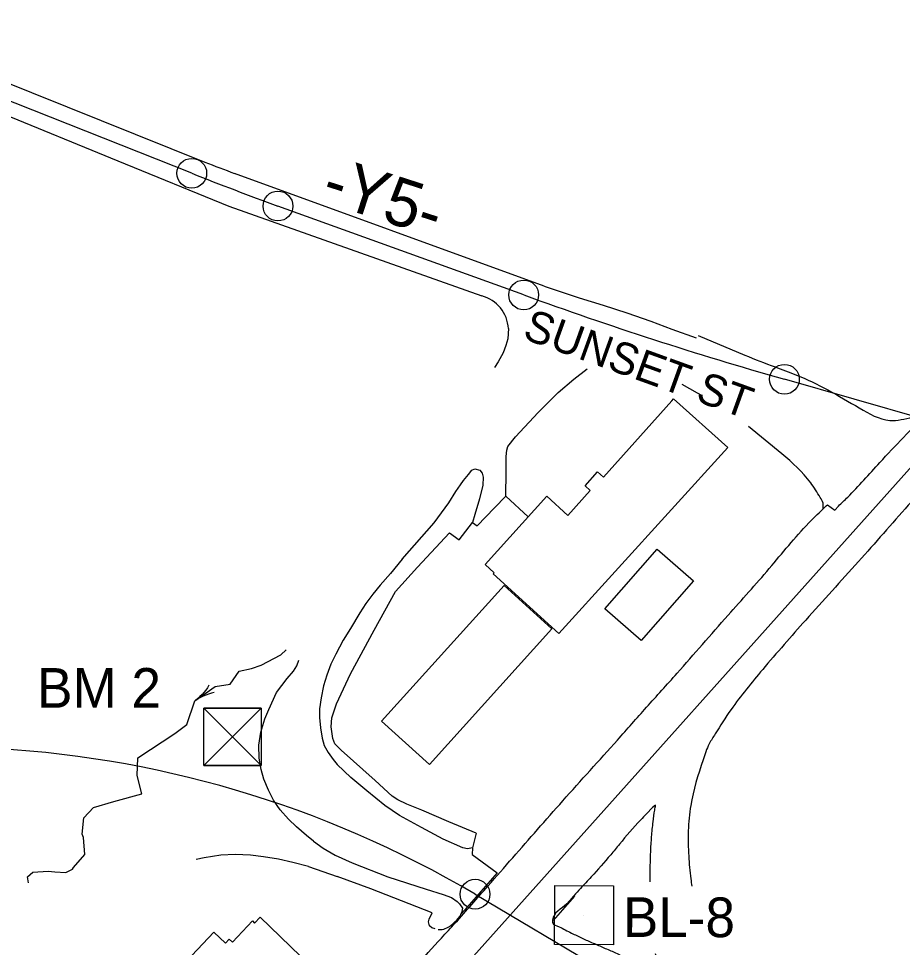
# Model space of a CAD drawing. Extents: x 2088830 to 2093930, y 861854 to 865154.
# Drawn here: x 2091668.1 to 2092113.5, y 863895.4 to 864363.2 of the extents above; entities that cross this region are included whole.
import ezdxf

# ---------------------------------------------------------------- set-up
doc = ezdxf.new("R2010")
doc.units = 0
for name, color, linetype in [('Default', 7, 'Continuous'), ('Exist Building', 7, 'Continuous'), ('Exist Building Metal Canopy', 7, 'Continuous'), ('Exist Horizontal Alignment', 7, 'Continuous'), ('Exist Horizontal Alignment Station Label', 7, 'Continuous'), ('Exist Hydro Stream Flow Arrow CELL', 7, 'Continuous'), ('Exist Hydro Stream or Body of Water', 7, 'Continuous'), ('Exist Roads Curbs', 7, 'Continuous'), ('Exist Roads EOP', 7, 'Continuous'), ('Exist Roads EOP Other', 7, 'Continuous'), ('Exist Roads Soil', 7, 'Continuous'), ('Exist Roads Soil Text', 7, 'Continuous')]:
    doc.layers.add(name, color=color, linetype=linetype)

msp = doc.modelspace()

# ---------------------------------------------------------------- linework, layer by layer
at = {"layer": 'Default'}
for p, q in [((2091668.57, 863635.39), (2092319.98, 864363.19)), ((2091755.37, 864285.26), (2091585.51, 864352.73)), ((2091922.65, 864223.98), (2091798.81, 864268.79)), ((2092136.35, 864158.02), (2092054.04, 864181.52)), ((2091775.92, 864001.45), (2091775.92, 864001.45)), ((2091898.12, 863922.18), (2091993.02, 863866.1)), ((2091952.99, 863911.67), (2091952.99, 863911.67))]:
    msp.add_line(p, q, dxfattribs=at)
for points in [[(2091761.52, 864015.8), (2091790.27, 864015.8), (2091790.27, 863987.05), (2091761.52, 863987.05)], [(2091938.32, 863926.5), (2091967.97, 863926.43), (2091967.9, 863896.73), (2091938.25, 863896.8)]]:
    msp.add_lwpolyline(points, close=True, dxfattribs=at)
for points in [[(2091790.27, 864015.8), (2091761.52, 863987.05), (2091775.9, 864001.43), (2091790.27, 863987.05), (2091761.52, 864015.8)], [(2091775.9, 864001.43), (2091790.27, 864015.8), (2091761.52, 864015.8), (2091775.9, 864001.43)], [(2091775.9, 864001.43), (2091761.52, 863987.05), (2091790.27, 863987.05), (2091775.9, 864001.43)]]:
    msp.add_lwpolyline(points, dxfattribs=at)
for centre, radius, start, end in [((2092309.09, 865679.32), 1500, 248.33706, 250.1116), ((2092603.03, 866104.7), 2000, 250.1116, 254.06813), ((2091626.97, 863463.31), 533, 59.4206, 115.7537)]:
    msp.add_arc(centre, radius, start, end, dxfattribs=at)
at = {"layer": 'Exist Building'}
for points in [[(2092025.57, 864147.09), (2091940.29, 864053.5), (2091907.31, 864083.55), (2091907.81, 864084.1), (2091903.21, 864088.27), (2091934.25, 864122.63), (2091944.9, 864112.99), (2091956.19, 864125.59), (2091953.59, 864127.93), (2091959.84, 864134.9), (2091962.84, 864132.21), (2091997.36, 864170.68), (2091998.21, 864171.63)], [(2091812.53, 863863.75), (2091770.26, 863818.18), (2091765.75, 863822.36), (2091760.12, 863816.27), (2091745.73, 863829.61), (2091750.24, 863834.41), (2091745.59, 863838.86), (2091746.7, 863840.03), (2091726.37, 863859.45), (2091750.65, 863884.73), (2091749.93, 863885.4), (2091766.52, 863903.07), (2091772.43, 863897.53), (2091774.3, 863899.52), (2091775.9, 863898.02), (2091785.95, 863908.72), (2091787.07, 863907.67), (2091789.91, 863910.58), (2091810.11, 863890.93), (2091797.71, 863878.18)]]:
    msp.add_lwpolyline(points, close=True, dxfattribs=at)
at = {"layer": 'Exist Building Metal Canopy'}
for points in [[(2092008.24, 864079.99), (2091981.86, 864049.93), (2091963.6, 864065.96), (2091989.97, 864096.01)], [(2091936.84, 864055.9), (2091875.11, 863987.57), (2091851.02, 864009.33), (2091912.76, 864077.66)]]:
    msp.add_lwpolyline(points, close=True, dxfattribs=at)
at = {"layer": 'Exist Horizontal Alignment Station Label'}
for centre in [(2091755.37, 864285.26), (2091798.81, 864268.79), (2091922.65, 864223.98), (2092054.04, 864181.52), (2091898.12, 863922.18)]:
    msp.add_circle(centre, 7.5, dxfattribs=at)
at = {"layer": 'Exist Hydro Stream Flow Arrow CELL'}
msp.add_line((2091761.3, 864022.67), (2091761.3, 864022.67), dxfattribs=at)
for points in [[(2091764.05, 864027.43), (2091763.3, 864026.17), (2091762.41, 864024.97), (2091761.51, 864023.79), (2091760.54, 864022.72), (2091759.49, 864021.68), (2091758.37, 864020.69), (2091757.22, 864019.78)], [(2091766.7, 864023.71), (2091765.26, 864023.42), (2091763.83, 864022.97), (2091762.42, 864022.51), (2091761.09, 864021.95), (2091759.76, 864021.29), (2091758.46, 864020.56), (2091757.22, 864019.78)]]:
    msp.add_lwpolyline(points, dxfattribs=at)
at = {"layer": 'Exist Hydro Stream or Body of Water'}
msp.add_lwpolyline([(2091673.04, 863927.91), (2091672.63, 863930.92), (2091675.3, 863933.32), (2091682.95, 863933.76), (2091686.37, 863933.48), (2091691.96, 863933.05), (2091695.28, 863934.85), (2091695.83, 863935.63), (2091701.52, 863942.14), (2091700.79, 863950.83), (2091700.07, 863952.46), (2091701.05, 863960.67), (2091705.84, 863965.84), (2091716.04, 863968.92), (2091730.16, 863972.74), (2091727.8, 863981.97), (2091728.22, 863990.87), (2091746.82, 864003.14), (2091752.9, 864007.72), (2091756.93, 864019.57), (2091767.09, 864026.79), (2091774.68, 864028.04), (2091779.21, 864034.48), (2091785.47, 864035.88), (2091790.32, 864037.56), (2091800.28, 864042.76), (2091802.98, 864045.29)], dxfattribs=at)
at = {"layer": 'Exist Roads Curbs'}
msp.add_lwpolyline([(2091948.2, 863921.2), (2091944.56, 863916.98), (2091937.42, 863908.98)], dxfattribs=at)
at = {"layer": 'Exist Roads EOP'}
msp.add_line((2091891.95, 863915.13), (2091890.46, 863917.34), dxfattribs=at)
for points in [[(2092075.7, 864118.27), (2092079.38, 864115.65), (2092081.27, 864117.7)], [(2091989.1, 863967.02), (2091987.62, 863965.86), (2091984.53, 863962.69)], [(2091909.32, 863932.89), (2091892.79, 863914.14), (2091891.36, 863912.45)]]:
    msp.add_lwpolyline(points, dxfattribs=at)
for points in [[(2092081.27, 864117.7), (2092085.95, 864122.17), (2092102.09, 864139.55), (2092125.96, 864164.87), (2092156.61, 864199.06), (2092190.08, 864236.15), (2092217.66, 864267.19), (2092246.02, 864298.82), (2092275.83, 864332.1), (2092303.35, 864363.16)], [(2092328.64, 864354.47), (2092320, 864344.96), (2092293.08, 864315.26), (2092283.58, 864304.8), (2092271.75, 864292.1), (2092254.33, 864272.28), (2092243.15, 864259.63), (2092226.98, 864241.41), (2092211.45, 864224.37), (2092183.27, 864193.04), (2092161.81, 864168.46), (2092139.48, 864143.81), (2092116.47, 864118.1), (2092091.34, 864089.69), (2092064.77, 864060.28), (2092043.08, 864035.35), (2092027.12, 864015.14), (2092019.12, 864002.89), (2092016.17, 863997.95), (2092013.03, 863989.85), (2092006.81, 863966.87), (2092005.58, 863954.12), (2092005.82, 863941.35), (2092006.84, 863930.01), (2092007.36, 863926.18)], [(2091734.18, 863736.92), (2091737.57, 863740.74), (2091742.7, 863746.41), (2091746.39, 863749.99), (2091752.74, 863757.34), (2091779.15, 863786.15), (2091800.43, 863809.86), (2091817.14, 863828.66), (2091827.31, 863840.06), (2091854.93, 863870.83), (2091881.2, 863900.12), (2091888.17, 863907.69), (2091904.65, 863926.31), (2091929.6, 863954.75), (2091942.38, 863969.24), (2091969.89, 863999.82), (2091984.53, 864016.32), (2091999.97, 864033.43), (2092012.73, 864047.99), (2092025.65, 864062.7), (2092046.42, 864086.24), (2092066.29, 864109.17), (2092073.24, 864116), (2092075.7, 864118.27)], [(2091984.53, 863962.69), (2091981.6, 863959.6), (2091970.91, 863947.39), (2091966.5, 863942.08), (2091956.66, 863930.9), (2091951.27, 863925.11), (2091947.85, 863921.37), (2091944.35, 863917.29), (2091937.14, 863909.25), (2091937.2, 863907.92), (2091940.52, 863905.82)], [(2091986.42, 863928.49), (2091986.4, 863932.93), (2091986.47, 863938.2), (2091986.65, 863943.46), (2091987.13, 863951.1), (2091987.88, 863958.71), (2091988.68, 863964.56), (2091989.1, 863967.02)], [(2091879.58, 863904.37), (2091880.86, 863904.4), (2091883.85, 863905.18), (2091887.84, 863908.07), (2091891.05, 863912), (2091891.95, 863915.13)], [(2091940.52, 863905.82), (2091946.75, 863902.64), (2091952.13, 863900.03), (2091957.58, 863897.59), (2091963.08, 863895.22), (2091965.82, 863894.02), (2091968.55, 863892.81), (2091980.94, 863887.15), (2091982.08, 863886.73), (2091983.28, 863886.46), (2091984.5, 863886.34), (2091985.11, 863886.33), (2091985.7, 863886.36), (2091987.76, 863886.97), (2091988.62, 863887.62), (2091988.95, 863888.04), (2091989.07, 863888.27), (2091989.18, 863888.52), (2091989.3, 863888.97), (2091989.36, 863890.31), (2091989.26, 863891.21), (2091989.14, 863892.1)]]:
    msp.add_spline(points, degree=3, dxfattribs=at)
at = {"layer": 'Exist Roads EOP Other'}
for points in [[(2091830.63, 863994.76), (2091827.43, 863997.96), (2091826.47, 864000.61), (2091825.69, 864006.48), (2091825.91, 864011.04), (2091828.35, 864018.06), (2091835.42, 864033.2), (2091847.32, 864055.21), (2091857.99, 864074.56), (2091869.16, 864086.97), (2091885.3, 864104.18), (2091890.18, 864100.7), (2091896.88, 864109.31), (2091899.21, 864107.63), (2091907.87, 864116.83), (2091913.63, 864122.58), (2091924.84, 864112.22)], [(2091898.71, 863952.88), (2091884.93, 863958.56), (2091871.3, 863964.52), (2091863.75, 863967.5), (2091859.2, 863969.64), (2091856.34, 863971.63), (2091847.85, 863979.48), (2091830.63, 863994.76)], [(2091898.71, 863952.88), (2091896.83, 863945.57), (2091896.64, 863942.25), (2091909.32, 863932.89)], [(2091878.11, 863904.72), (2091876.27, 863905.32), (2091875.18, 863906.2), (2091874.61, 863908.26), (2091874.95, 863909.64), (2091876.45, 863912.87), (2091845.64, 863924.82), (2091828.61, 863931.03)]]:
    msp.add_lwpolyline(points, dxfattribs=at)
at = {"layer": 'Exist Roads Soil'}
for p, q in [((2091616.34, 864349.21), (2091761.96, 864290.93)), ((2091654.68, 864317.48), (2091718.07, 864291.58)), ((2091718.07, 864291.58), (2091774.06, 864268.7)), ((2091932.99, 864228.49), (2091776.95, 864285.2)), ((2091774.06, 864268.7), (2091901.48, 864223.48)), ((2092010.55, 864203.65), (2092034.01, 864193.68)), ((2092052.76, 864144.01), (2092035.93, 864157.81)), ((2091897.94, 864113.34), (2091896.88, 864109.31)), ((2091814.23, 863936.09), (2091828.61, 863931.03))]:
    msp.add_line(p, q, dxfattribs=at)
for points in [[(2091932.99, 864228.49), (2091950.66, 864222.62), (2091962.74, 864218.85), (2091974.68, 864215.02), (2091986.8, 864210.83), (2091997.29, 864206.81), (2092009.63, 864202.38)], [(2091914.93, 864207.11), (2091914.69, 864201.83), (2091913.71, 864198.61), (2091912.27, 864194.76), (2091909.76, 864190.25), (2091907.98, 864187.49)], [(2091913.63, 864122.58), (2091913.74, 864134.95), (2091913.85, 864142.59), (2091914.08, 864145.89), (2091914.62, 864147.64), (2091918.44, 864152.53), (2091929.87, 864164.85), (2091939.94, 864174.81), (2091947.96, 864181.64), (2091954.7, 864186.73)], [(2092012.73, 864173.11), (2092010.3, 864174.6), (2092002.47, 864178.88)], [(2091861.47, 864090.93), (2091877.56, 864109.25), (2091884.9, 864119.3), (2091888.46, 864124.95), (2091890.88, 864128.32), (2091892.34, 864130.57), (2091894.77, 864133.57), (2091896.48, 864135.7), (2091898.07, 864136.49), (2091900.58, 864135.76), (2091901.79, 864134.29), (2091902.29, 864132.18), (2091902.02, 864128.16), (2091900.45, 864121.39), (2091897.94, 864113.34)], [(2091861.47, 864090.93), (2091855.52, 864083.67), (2091850.31, 864077.81), (2091846.63, 864073.23), (2091843.14, 864068.62), (2091840.05, 864063.84), (2091835.37, 864056.01), (2091831.63, 864050.17), (2091827.92, 864043.13), (2091825.53, 864038.12), (2091823.52, 864032.55), (2091821.75, 864027.06), (2091820.51, 864021.09), (2091819.77, 864015.62), (2091819.75, 864011.25), (2091820.23, 864005.91), (2091821.1, 864000.84), (2091822.14, 863997.01), (2091824.03, 863993.53), (2091826.64, 863990.06), (2091828.69, 863987.57)], [(2091816.7, 863948.93), (2091813.2, 863951.8), (2091808.21, 863956.05), (2091804.09, 863959.94), (2091799.88, 863964.6), (2091796.51, 863969.49), (2091794.05, 863974.6), (2091791.75, 863980.15), (2091790.33, 863985.03), (2091789.34, 863990.75), (2091789.25, 863997.29), (2091790.13, 864003.74), (2091792.16, 864010.53), (2091794.26, 864015.25), (2091798.14, 864023.72), (2091803.45, 864030.83), (2091806.69, 864034.55), (2091808.39, 864037.23), (2091809.31, 864040.14)], [(2091896.83, 863945.57), (2091894.27, 863945.05), (2091891.93, 863945.58), (2091882.04, 863949.85), (2091871.08, 863955.83), (2091860.14, 863961.89), (2091852.72, 863966.94), (2091843.52, 863974.32), (2091835.61, 863981.02), (2091828.69, 863987.57)], [(2091816.7, 863948.93), (2091821.53, 863945.36), (2091827.63, 863941.86), (2091836.14, 863938.06), (2091854.17, 863930.92), (2091873.47, 863924.65), (2091882.04, 863921.98), (2091886.28, 863920.46), (2091889.14, 863918.57), (2091890.37, 863917.3)], [(2091814.23, 863936.09), (2091806.35, 863938.16), (2091799.13, 863939.77), (2091791.57, 863941.09), (2091785, 863941.8), (2091777.28, 863942.15), (2091769.98, 863941.87), (2091761.61, 863940.54), (2091757.64, 863939.63)]]:
    msp.add_lwpolyline(points, dxfattribs=at)
for centre, radius, start, end in [((2091947.75, 864755.13), 500, 248.187, 250.0257), ((2091897.12, 864206.2), 17.83, 2.7401, 75.8362)]:
    msp.add_arc(centre, radius, start, end, dxfattribs=at)
for points in [[(2092034.01, 864193.68), (2092049.32, 864187.71), (2092059.8, 864183.8), (2092091.79, 864167.06), (2092107.12, 864160.81), (2092118.62, 864162.54)], [(2092073.43, 864116.55), (2092073.53, 864117.3), (2092073.49, 864119.17), (2092072.1, 864121.98), (2092067.27, 864129.41), (2092052.76, 864144.01)]]:
    msp.add_spline(points, degree=3, dxfattribs=at)

# ---------------------------------------------------------------- texts
at = {"layer": 'Default'}
msp.add_text('BM 2', height=20, dxfattribs=at).set_placement((2091677.43, 864016.08))
msp.add_text('BL-8', height=20, rotation=359.8423, dxfattribs=at).set_placement((2091972.61, 863900.68))
at = {"layer": 'Exist Horizontal Alignment'}
msp.add_text('-Y5-', height=24, rotation=342.1518, dxfattribs=at).set_placement((2091819.74, 864271.46))
at = {"layer": 'Exist Roads Soil Text'}
msp.add_text('SUNSET ST', height=16, rotation=340.1457, dxfattribs=at).set_placement((2091921.49, 864202.24))

doc.saveas('drawing.dxf')
